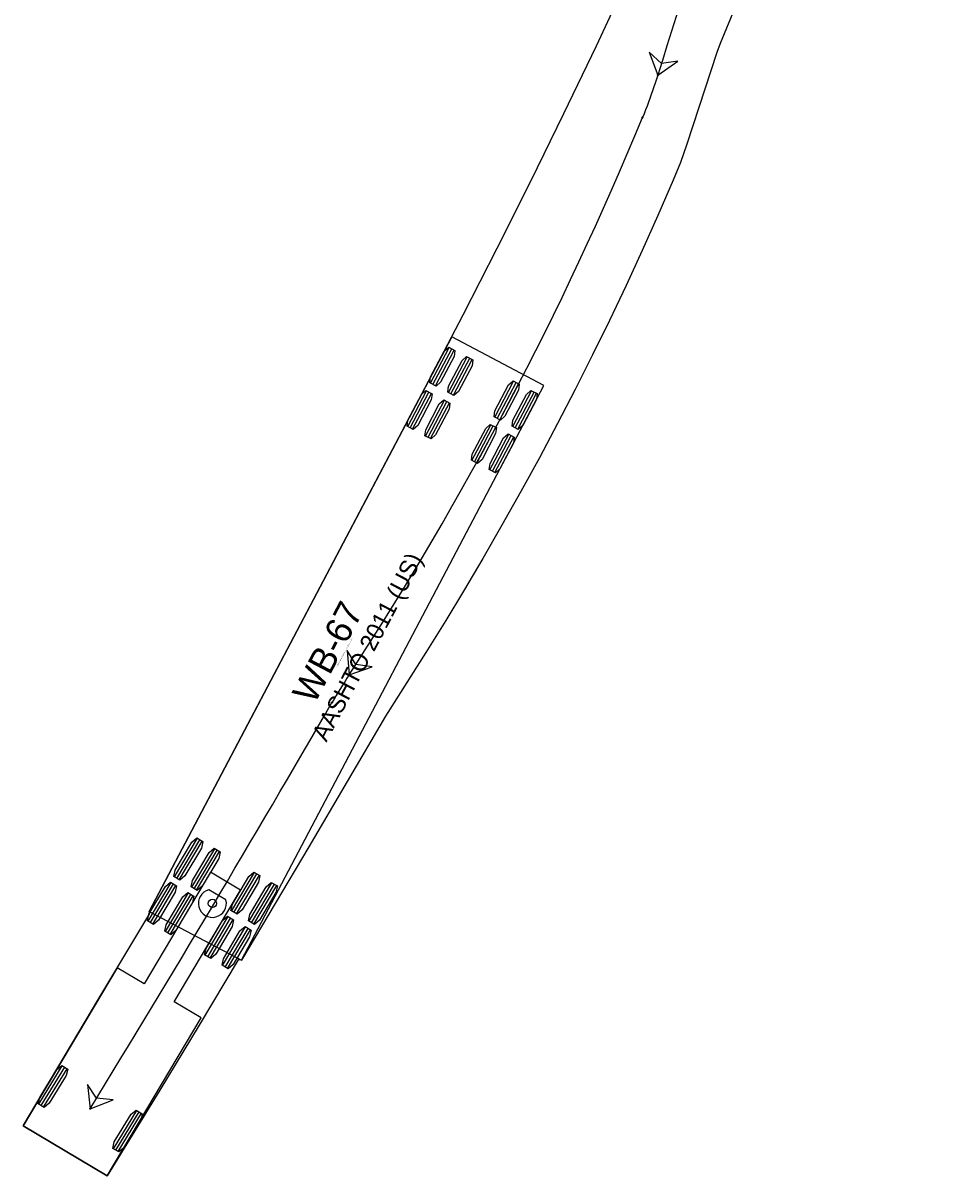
# Model space of a CAD drawing. Extents: x 2175591 to 2194071, y 76570 to 86955.
# Drawn here: x 2176982.4 to 2177056.9, y 78044.2 to 78138.2 of the extents above; entities that cross this region are included whole.
import ezdxf

# ---------------------------------------------------------------- set-up
doc = ezdxf.new("R2010")
doc.units = 0
doc.layers.add('C-UTIL-STRM-TEXT', color=7, linetype='Continuous')

msp = doc.modelspace()

# ---------------------------------------------------------------- linework, layer by layer
at = {"layer": 'C-UTIL-STRM-TEXT'}
for p, q in [((2177017.43, 78112.615), (2176992.74, 78065.717)), ((2177024.951, 78108.655), (2177017.43, 78112.615)), ((2177015.699, 78108.836), (2177017.236, 78111.756)), ((2177015.902, 78108.729), (2177017.439, 78111.649)), ((2177016.105, 78108.622), (2177017.642, 78111.542)), ((2177017.159, 78108.067), (2177018.696, 78110.987)), ((2177017.362, 78107.96), (2177018.899, 78110.88)), ((2177017.565, 78107.854), (2177019.102, 78110.774)), ((2177000.261, 78061.757), (2177024.951, 78108.655)), ((2177013.836, 78105.296), (2177015.373, 78108.216)), ((2177020.949, 78106.072), (2177022.487, 78108.992)), ((2177021.152, 78105.965), (2177022.689, 78108.885)), ((2177021.355, 78105.858), (2177022.892, 78108.778)), ((2177022.409, 78105.303), (2177023.947, 78108.223)), ((2177022.612, 78105.196), (2177024.149, 78108.116)), ((2177014.038, 78105.19), (2177015.576, 78108.11)), ((2177014.241, 78105.083), (2177015.779, 78108.003)), ((2177015.296, 78104.528), (2177016.833, 78107.448)), ((2177015.499, 78104.421), (2177017.036, 78107.341)), ((2177015.701, 78104.314), (2177017.239, 78107.234)), ((2177022.815, 78105.09), (2177024.352, 78108.01)), ((2177019.086, 78102.532), (2177020.623, 78105.452)), ((2177019.289, 78102.426), (2177020.826, 78105.346)), ((2177019.491, 78102.319), (2177021.029, 78105.239)), ((2177020.546, 78101.764), (2177022.083, 78104.684)), ((2177020.749, 78101.657), (2177022.286, 78104.577)), ((2177020.952, 78101.55), (2177022.489, 78104.47)), ((2176994.794, 78068.549), (2176996.669, 78071.7)), ((2176994.991, 78068.432), (2176996.866, 78071.583)), ((2176995.188, 78068.315), (2176997.063, 78071.466)), ((2176996.212, 78067.705), (2176998.087, 78070.856)), ((2176996.409, 78067.588), (2176998.284, 78070.739)), ((2176996.606, 78067.471), (2176998.481, 78070.622)), ((2176997.74, 78068.929), (2176992.319, 78059.821)), ((2177000.204, 78067.463), (2176997.74, 78068.929)), ((2176999.463, 78065.77), (2177001.338, 78068.921)), ((2176999.66, 78065.653), (2177001.535, 78068.804)), ((2176999.857, 78065.536), (2177001.732, 78068.687)), ((2176992.646, 78064.94), (2176994.521, 78068.091)), ((2176992.843, 78064.823), (2176994.718, 78067.974)), ((2176993.04, 78064.706), (2176994.915, 78067.857)), ((2177000.881, 78064.927), (2177002.756, 78068.077)), ((2177001.078, 78064.809), (2177002.953, 78067.96)), ((2177001.275, 78064.692), (2177003.15, 78067.843)), ((2176994.064, 78064.096), (2176995.939, 78067.247)), ((2176994.261, 78063.979), (2176996.136, 78067.13)), ((2176994.458, 78063.862), (2176996.333, 78067.013)), ((2176994.782, 78058.354), (2177000.204, 78067.463)), ((2176999.006, 78066.673), (2176997.617, 78067.499)), ((2176992.74, 78065.717), (2177000.261, 78061.757)), ((2176997.315, 78062.161), (2176999.19, 78065.312)), ((2176997.512, 78062.044), (2176999.387, 78065.195)), ((2176997.709, 78061.927), (2176999.584, 78065.078)), ((2176998.733, 78061.317), (2177000.608, 78064.468)), ((2176998.93, 78061.2), (2177000.805, 78064.351)), ((2176999.127, 78061.083), (2177001.002, 78064.234)), ((2176990.113, 78061.133), (2176982.442, 78048.244)), ((2176992.319, 78059.821), (2176990.113, 78061.133)), ((2177000.261, 78061.757), (2177000.261, 78061.757)), ((2176996.988, 78057.042), (2176994.782, 78058.354)), ((2176989.316, 78044.152), (2176996.988, 78057.042)), ((2176983.731, 78050.007), (2176985.646, 78053.135)), ((2176983.927, 78049.888), (2176985.841, 78053.015)), ((2176984.122, 78049.768), (2176986.037, 78052.895)), ((2176989.812, 78046.375), (2176991.727, 78049.502)), ((2176990.008, 78046.255), (2176991.922, 78049.382)), ((2176990.203, 78046.135), (2176992.118, 78049.263)), ((2176982.442, 78048.244), (2176989.316, 78044.152)), ((2176989.316, 78044.152), (2176989.316, 78044.152))]:
    msp.add_line(p, q, dxfattribs=at)
for points in [[(2177056.876, 78178.949), (2177039.348, 78136.552), (2177039.065, 78135.823), (2177036.621, 78128.344), (2177036.1, 78126.858), (2177035.516, 78125.4), (2177034.263, 78122.521), (2177032.976, 78119.655), (2177031.658, 78116.803), (2177030.307, 78113.964), (2177028.924, 78111.14), (2177027.509, 78108.33), (2177026.062, 78105.536), (2177024.584, 78102.758), (2177023.074, 78099.996), (2177021.534, 78097.251), (2177019.97, 78094.536), (2177018.394, 78091.868), (2177016.948, 78089.479), (2177015.327, 78086.861), (2177012.021, 78081.678), (2177008.91, 78076.348), (2177005.763, 78070.999), (2177000.261, 78061.757), (2177000.011, 78061.782), (2176996.818, 78056.464), (2176993.604, 78051.159), (2176989.316, 78044.152), (2176982.442, 78048.244), (2176988.621, 78058.626), (2176992.777, 78065.569), (2176992.74, 78065.717), (2177015.53, 78109.007), (2177018.354, 78114.422), (2177021.14, 78119.864), (2177023.885, 78125.335), (2177026.586, 78130.837), (2177029.24, 78136.372), (2177031.836, 78141.935)], [(2177034.245, 78133.966), (2177034.145, 78133.648), (2177034.043, 78133.331), (2177033.938, 78133.014), (2177033.83, 78132.699), (2177033.72, 78132.384), (2177033.608, 78132.07), (2177033.493, 78131.757), (2177033.376, 78131.445), (2177033.256, 78131.134), (2177033.133, 78130.824), (2177033.008, 78130.516)], [(2177009.063, 78085.041), (2177008.881, 78084.761), (2177008.7, 78084.481), (2177008.522, 78084.199), (2177008.345, 78083.917), (2177008.171, 78083.633), (2177007.998, 78083.347), (2177007.827, 78083.061), (2177007.659, 78082.774)]]:
    msp.add_lwpolyline(points, dxfattribs=at)
for points in [[(2177034.245, 78133.966), (2177035.883, 78135.113), (2177034.546, 78134.92), (2177033.561, 78135.845)], [(2177016.155, 78108.596), (2177015.649, 78108.862), (2177015.712, 78109.351), (2177016.818, 78111.454), (2177017.186, 78111.782), (2177017.692, 78111.516), (2177017.63, 78111.027), (2177016.523, 78108.924)], [(2177017.615, 78107.827), (2177017.109, 78108.094), (2177017.172, 78108.583), (2177018.278, 78110.685), (2177018.646, 78111.014), (2177019.152, 78110.747), (2177019.09, 78110.258), (2177017.983, 78108.156)], [(2177014.292, 78105.056), (2177013.785, 78105.323), (2177013.848, 78105.812), (2177014.955, 78107.914), (2177015.323, 78108.243), (2177015.829, 78107.976), (2177015.766, 78107.487), (2177014.659, 78105.385)], [(2177021.405, 78105.832), (2177020.899, 78106.098), (2177020.962, 78106.587), (2177022.069, 78108.69), (2177022.436, 78109.018), (2177022.942, 78108.752), (2177022.88, 78108.263), (2177021.773, 78106.16)], [(2177022.865, 78105.063), (2177022.359, 78105.33), (2177022.422, 78105.819), (2177023.529, 78107.921), (2177023.896, 78108.25), (2177024.402, 78107.983), (2177024.34, 78107.494), (2177023.233, 78105.392)], [(2177015.752, 78104.288), (2177015.245, 78104.554), (2177015.308, 78105.043), (2177016.415, 78107.146), (2177016.783, 78107.474), (2177017.289, 78107.208), (2177017.226, 78106.719), (2177016.119, 78104.616)], [(2177019.542, 78102.292), (2177019.036, 78102.559), (2177019.098, 78103.048), (2177020.205, 78105.15), (2177020.573, 78105.479), (2177021.079, 78105.212), (2177021.016, 78104.723), (2177019.909, 78102.621)], [(2177021.002, 78101.524), (2177020.496, 78101.79), (2177020.558, 78102.279), (2177021.665, 78104.382), (2177022.033, 78104.71), (2177022.539, 78104.444), (2177022.476, 78103.955), (2177021.37, 78101.852)], [(2177009.063, 78085.041), (2177010.949, 78085.705), (2177009.609, 78085.878), (2177008.909, 78087.035)], [(2176995.237, 78068.286), (2176994.745, 78068.578), (2176994.86, 78069.108), (2176996.21, 78071.376), (2176996.621, 78071.729), (2176997.112, 78071.437), (2176996.998, 78070.907), (2176995.647, 78068.639)], [(2176996.655, 78067.442), (2176996.163, 78067.734), (2176996.278, 78068.264), (2176997.628, 78070.532), (2176998.038, 78070.885), (2176998.53, 78070.593), (2176998.415, 78070.063), (2176997.065, 78067.795)], [(2176999.906, 78065.507), (2176999.414, 78065.799), (2176999.529, 78066.329), (2177000.879, 78068.597), (2177001.289, 78068.95), (2177001.781, 78068.658), (2177001.667, 78068.128), (2177000.316, 78065.86)], [(2176993.089, 78064.677), (2176992.597, 78064.969), (2176992.712, 78065.499), (2176994.062, 78067.767), (2176994.472, 78068.12), (2176994.964, 78067.828), (2176994.849, 78067.298), (2176993.499, 78065.03)], [(2177001.323, 78064.663), (2177000.832, 78064.956), (2177000.946, 78065.485), (2177002.297, 78067.753), (2177002.707, 78068.106), (2177003.199, 78067.814), (2177003.084, 78067.285), (2177001.734, 78065.016)], [(2176994.506, 78063.833), (2176994.015, 78064.125), (2176994.129, 78064.655), (2176995.48, 78066.923), (2176995.89, 78067.276), (2176996.382, 78066.984), (2176996.267, 78066.454), (2176994.917, 78064.186)], [(2176997.758, 78061.898), (2176997.266, 78062.19), (2176997.38, 78062.72), (2176998.731, 78064.988), (2176999.141, 78065.341), (2176999.633, 78065.049), (2176999.518, 78064.519), (2176998.168, 78062.251)], [(2176999.175, 78061.054), (2176998.684, 78061.346), (2176998.798, 78061.876), (2177000.149, 78064.144), (2177000.559, 78064.497), (2177001.051, 78064.205), (2177000.936, 78063.675), (2176999.586, 78061.407)], [(2176984.171, 78049.738), (2176983.683, 78050.037), (2176983.804, 78050.565), (2176985.182, 78052.816), (2176985.597, 78053.164), (2176986.085, 78052.866), (2176985.964, 78052.338), (2176984.586, 78050.086)], [(2176987.925, 78049.635), (2176989.791, 78050.353), (2176988.447, 78050.488), (2176987.715, 78051.624)], [(2176990.252, 78046.106), (2176989.764, 78046.404), (2176989.885, 78046.932), (2176991.263, 78049.184), (2176991.678, 78049.532), (2176992.166, 78049.233), (2176992.045, 78048.705), (2176990.667, 78046.454)]]:
    msp.add_lwpolyline(points, close=True, dxfattribs=at)
for centre, radius in [((2177034.245, 78133.966), 0.0417), ((2177034.245, 78133.966), 0.0417), ((2177033.008, 78130.516), 0.0417), ((2177033.008, 78130.516), 0.0417), ((2177009.063, 78085.041), 0.0417), ((2177009.063, 78085.041), 0.0417), ((2177007.659, 78082.774), 0.0417), ((2177007.659, 78082.774), 0.0417), ((2176997.898, 78066.392), 0.34), ((2176987.925, 78049.635), 0.0417)]:
    msp.add_circle(centre, radius, dxfattribs=at)
for centre, radius, start, end in [((2178767.681, 77587.578), 1817.509, 161.237072, 162.504865), ((2176777.002, 78236.277), 276.991, 326.90726, 337.55346), ((2175638.901, 78875.435), 1581.711, 328.527268, 329.924441), ((2176997.898, 78066.392), 1.143, 104.23921, 14.23921)]:
    msp.add_arc(centre, radius, start, end, dxfattribs=at)

# ---------------------------------------------------------------- texts
for s, height, p in [('AASHTO 2011 (US)', 1.41667, (2177007.208, 78079.5)), ('WB-67', 2.125, (2177006.22, 78082.564)), ('(c) 2019 Transoft Solutions, Inc. All rights reserved.', 0.085, (2177008.076, 78085.633))]:
    msp.add_text(s, height=height, rotation=62.23502, dxfattribs=at).set_placement(p)

doc.saveas('drawing.dxf')
